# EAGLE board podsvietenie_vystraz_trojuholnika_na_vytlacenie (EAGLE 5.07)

Size 7 x 12 mm. Coordinates in mm from the lower left corner, seen from the top.
Outline: 0,0 7,0 7,12 0,12 0,0
Copper layers (1*16): Top 0.035mm / dielectric 1.5mm / Bottom 0.035mm
Design rules "default *": minimum track width 10mil, minimum drill 24mil, track to track 8mil, track to pad 8mil, pad to pad 8mil, via to via 8mil, smd to smd 8mil, copper to edge 40mil, drill to drill 8mil, minimum pad ring 12mil, minimum via ring 8mil, stop-mask expansion 4mil, vias tented up to drill 0mil, thermal gap 10mil

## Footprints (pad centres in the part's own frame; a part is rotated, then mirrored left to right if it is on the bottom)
1206 = smd 1.6 x 1.803: A -1.422,0; C 1.422,0
1206' = smd 1.143 x 1.702: 1 -1.587,0; 2 1.587,0

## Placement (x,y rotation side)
LED1  [1206]  5.7,5.22 270 top
R1  [1206']  1.5,8 90 top

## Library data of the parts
LED1 = led
R1 = #PaJa_21

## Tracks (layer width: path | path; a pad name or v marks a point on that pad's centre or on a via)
(copper drawn outside any net)
  shapes: Bottom area x4

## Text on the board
Bottom: 0V | +12V
tNames: by FoXo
